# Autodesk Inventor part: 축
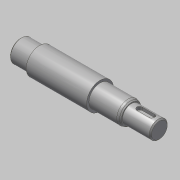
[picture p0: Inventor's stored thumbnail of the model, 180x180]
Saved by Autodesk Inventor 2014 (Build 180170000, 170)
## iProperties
Created: 2016-06
Part Number: 축
Material: 강철, 연강
Document SubType Name: Modeling
Designer: mduedu
Density: 7.86 g/cm^3
Appearance: Steel
Author: mduedu
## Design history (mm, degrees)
sketch "스케치1"
  geometry: L1 (-62, 0)-(62, 0); L2 (-62, 0)-(-62, 10); L3 (-62, 10)-(-45, 10); L4 (-45, 10)-(-45, 12); L5 (-45, 12)-(9, 12); L6 (9, 12)-(9, 10); L7 (9, 10)-(37, 10); L8 (37, 10)-(37, 8); L9 (37, 8)-(62, 8); L10 (62, 8)-(62, 0); 2 further points
  constraints: 20 end point, 5 parallel, 2 perpendicular, 1 coincident, 1 collinear, 1 horizontal, 1 midpoint, 1 vertical
  dimensions: "d0" = 124 distance of L1.start L1.end; "d2" = 16 diameter of L9 L1; "d3" = 20 diameter of L7 L1; "d4" = 24 diameter of L5 L1; "d5" = 20 diameter of L3 L1; "d6" = 17 distance of L2.end L3.end; "d7" = 25 distance of L8.end L9.end; "d8" = 53 distance from line of L5.end L10
revolve "회전1" sketch "스케치1" stored, may be unused: angle "d9" = 90 deg
chamfer "모따기1" distance "d10" = 2; stored, may be unused: second distance "d11" = 2, angle "d12" = 30 deg
fillet "모깎기1" dims "d13" = 4
node "작업 평면1"
sketch "스케치2"
  geometry: L1 (-5, 2.5)-(6, 2.5); L2 (6, -2.5)-(-5, -2.5); L3 (-5, 0)-(6, 0); L4 (-12.5, 8.845)-(-12.5, -8.845) reference; A1 r 2.5 centre (-5, 0) between (-5, 2.5) and (-5, -2.5); A2 r 2.5 centre (6, 0) between (6, -2.5) and (6, 2.5); 1 further point
  constraints: 6 end point, 4 point on circle, 3 tangent, 2 centre point, 2 parallel, 1 horizontal, 1 horizontal alignment
  dimensions: "d14" = 5 distance edge to line of A1 L4; "d15" = 5 distance between parallel lines of L2 L1; "d16" = 16 dimension on A2 A1
extrude "돌출1" cut sketch "스케치2" distance "d17" = 3; taper "d18" = 0 deg
chamfer "모따기2" distance "d19" = 1; stored, may be unused: second distance "d20" = 2, angle "d21" = 30 deg
sketch "스케치3"
  geometry: L1 (-37, -8)-(-61, -8) reference; L2 (-62, -7)-(-62, 7) reference; L3 (-38.5, -8)-(-40, -6.5); L4 (-40, -6.5)-(-40, -8); L5 (-38.5, -8)-(-40, -8); 1 further point
  constraints: 6 end point, 2 point on line, 1 collinear, 1 vertical
  dimensions: "d22" = 45 deg angle of L4 L3; "d23" = 22 distance between parallel lines of L2 L4; "d24" = 3 diameter of L3.start L4
revolve "회전2" stored, may be unused: angle "d25" = 90 deg
node "작업점1"
sketch "스케치4"
  geometry: 1 further point
hole "구멍1" sketch "스케치4" at (0, 0) diameter "d26" = 3.242; stored, may be unused: countersink angle "d30" = 90 deg, drill point angle "d32" = 120 deg; dims "d27" = 8, "d28" = 4, "d29" = 2, "d31" = 11
chamfer "모따기3" distance "d33" = 2; stored, may be unused: second distance "d34" = 2, angle "d35" = 30 deg
node "솔리드1"
